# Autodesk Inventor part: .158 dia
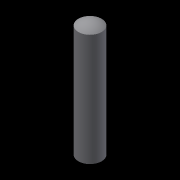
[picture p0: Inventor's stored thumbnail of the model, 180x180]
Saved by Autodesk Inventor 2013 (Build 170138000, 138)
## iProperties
Created: 2013-01
Part Number: .158 dia
Material: Generic
Document SubType Name: Modeling
Designer: John
Density: 1 g/cm^3
Author: John
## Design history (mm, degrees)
sketch "Sketch1"
  geometry: L1 (0, 0)-(0, 19.355); L2 (4.013, 0)-(4.013, 19.355) reference; L3 (2.007, -0.714)-(2.007, 20.069); A1 r 3.175 centre (2.007, 16.894) between (4.013, 19.355) and (2.007, 20.069); A2 r 3.175 centre (2.007, 2.461) between (2.007, -0.714) and (4.013, 0)
  constraints: 6 end point, 4 point on circle, 2 centre point, 2 vertical
  dimensions: "d2" = 3.175 radius of A1; "d3" = 3.175 radius of A2
revolve "Revolution1" sketch "Sketch1" stored, may be unused: angle "d4" = 90 deg
body "Solid1"
